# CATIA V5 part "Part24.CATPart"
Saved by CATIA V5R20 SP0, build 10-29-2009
Part number: 9FP040612-20130117
Revision: ANY
Definition: UNKNOWN
Nomenclature: 9FP040612-20130117
Source: Unknown
Bounding box of the stored display mesh (mm): x -6 to 6, y -6 to 5.85, z 0 to 8
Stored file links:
  C:\Users\Utente\Desktop\IO LAVORO\3D X SITO CF\CUMSA\3D files PF\PF 064200\Part24.CATPart
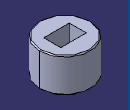
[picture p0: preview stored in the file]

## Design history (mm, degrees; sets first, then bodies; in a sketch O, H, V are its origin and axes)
Body1 "Chaflán1" (main body)
  Solid1: solid without history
